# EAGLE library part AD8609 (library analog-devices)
Precision Micropower, Low Noise CMOS, Rail-to-Rail Input/Output Operational Amplifiers Source: http://www.analog.com/static/imported-files/data_sheets/AD8603_8607_8609.pdf
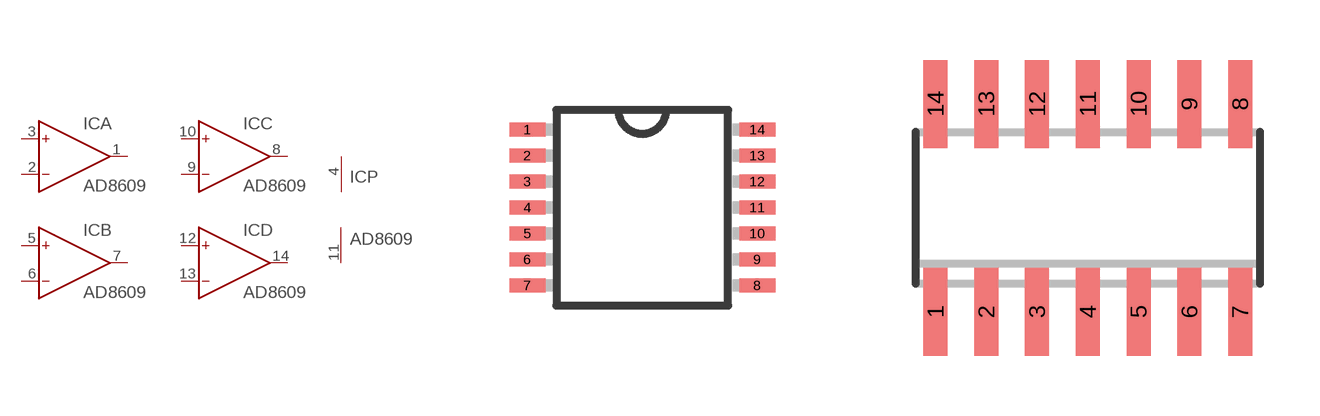
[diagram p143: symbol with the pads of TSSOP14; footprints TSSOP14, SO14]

Designator prefix IC; gates A=OP B=OP C=OP D=OP P=PWR+-

## AD8609RU (MF: ALTERA CORPORATION; MPN: AD8609ARUZ; OC_FARNELL: 1464994; OC_NEWARK: 59K6934)  [TSSOP14]
1  A:OUT  out
2  A:IN-  in
3  A:IN+  in
4  P:V+  pwr
5  B:IN+  in
6  B:IN-  in
7  B:OUT  out
8  C:OUT  out
9  C:IN-  in
10  C:IN+  in
11  P:V-  pwr
12  D:IN+  in
13  D:IN-  in
14  D:OUT  out

## AD8609R (MPN: AD8609ARZ; OC_FARNELL: 1581951; OC_NEWARK: 19M0976)  [SO14]
Pads as for TSSOP14

## Footprint TSSOP14 (pad centres in mm)
14-Lead Thin Shrink Small Outline Package [TSSOP] Source: Analog Devices .. 780914713ADD8704_0.pdf
smd 0.9 x 0.35: 1 -2.875,1.95; 2 -2.875,1.3; 3 -2.875,0.65; 4 -2.875,0; 5 -2.875,-0.65; 6 -2.875,-1.3; 7 -2.875,-1.95; 8 2.875,-1.95; 9 2.875,-1.3; 10 2.875,-0.65; 11 2.875,0; 12 2.875,0.65; 13 2.875,1.3; 14 2.875,1.95

## Footprint SO14 (pad centres in mm)
14-Lead Narrow-Body SOIC (SO-14) Source: http://www.analog.com/static/imported-files/data_sheets/SSM2166.pdf
smd 0.6 x 2.2: 1 -3.81,-2.6; 2 -2.54,-2.6; 3 -1.27,-2.6; 4 0,-2.6; 5 1.27,-2.6; 6 2.54,-2.6; 7 3.81,-2.6; 8 3.81,2.6; 9 2.54,2.6; 10 1.27,2.6; 11 0,2.6; 12 -1.27,2.6; 13 -2.54,2.6; 14 -3.81,2.6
